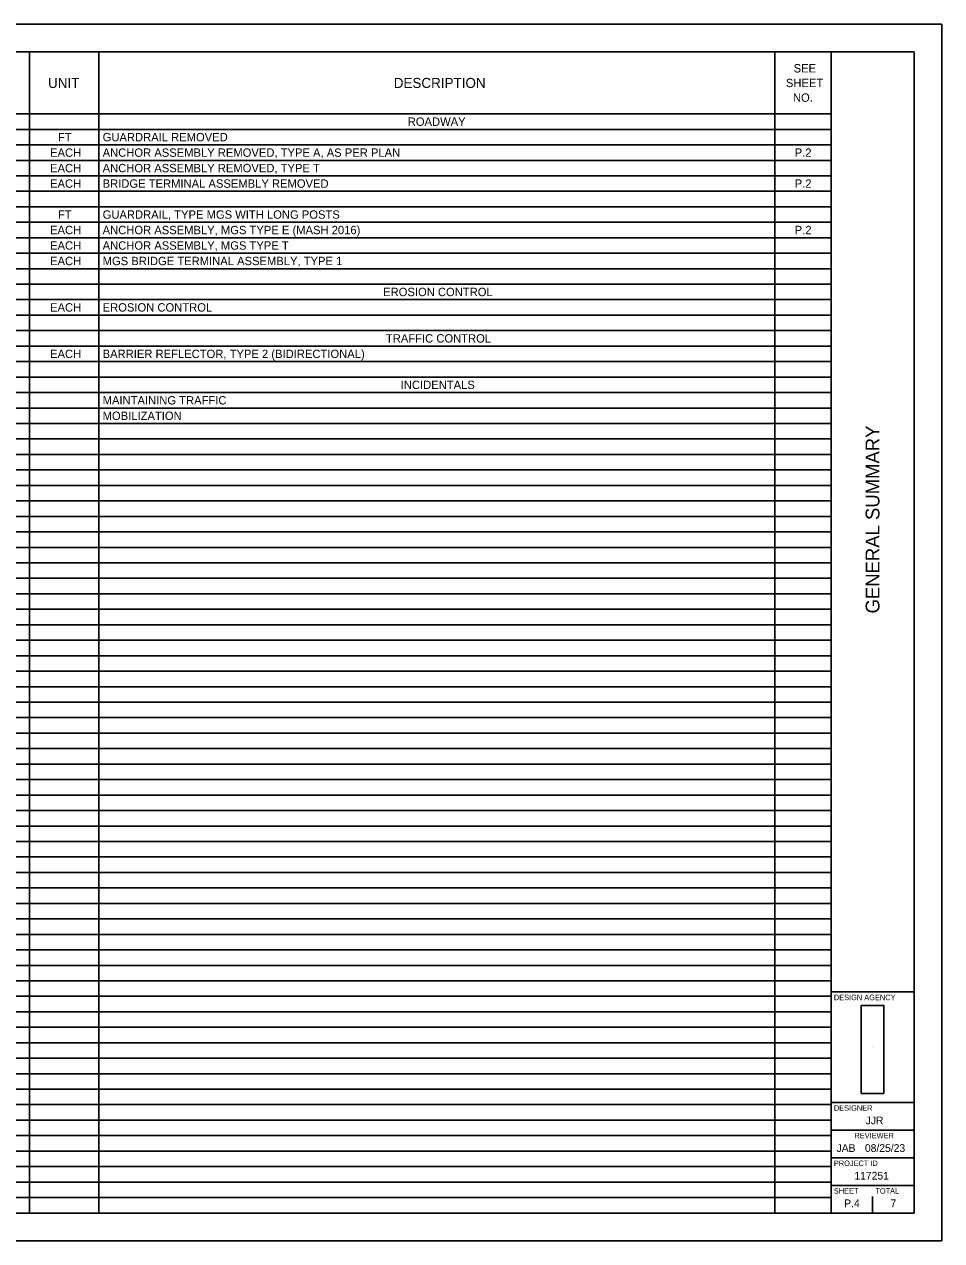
# Model space of a CAD drawing. Extents: x 0 to 34, y 0 to 22.
# Drawn here: x 17.41 to 34, y 0 to 22 of the extents above; entities that cross this region are included whole.
import ezdxf

# ---------------------------------------------------------------- set-up
doc = ezdxf.new("R2010")
doc.units = 0
for name, color, linetype in [('SH_Border', 7, 'Continuous'), ('SH_Cut_Line', 7, 'Continuous'), ('SH_Data', 7, 'Continuous'), ('SH_Text', 7, 'Continuous')]:
    doc.layers.add(name, color=color, linetype=linetype)

msp = doc.modelspace()

# ---------------------------------------------------------------- linework, layer by layer
at = {"layer": 'SH_Border'}
for p, q in [((32, 0.5), (32, 21.5)), ((32, 4.5), (33.5, 4.5)), ((32, 2.5), (33.5, 2.5)), ((32, 2), (33.5, 2)), ((32, 1.5), (33.5, 1.5)), ((32, 1), (33.5, 1))]:
    msp.add_line(p, q, dxfattribs=at)
msp.add_lwpolyline([(1.5, 21.5), (33.5, 21.5), (33.5, 0.5), (1.5, 0.5)], close=True, dxfattribs=at)
at = {"layer": 'SH_Cut_Line'}
msp.add_lwpolyline([(0, 0), (34, 0), (34, 22), (0, 22)], close=True, dxfattribs=at)
at = {"layer": 'SH_Data'}
for p, q in [((32.75, 3.5), (32.75, 3.5)), ((32.375, 0.675), (32.375, 0.675)), ((32.75, 0.5), (32.75, 0.8))]:
    msp.add_line(p, q, dxfattribs=at)
at = {"layer": 'SH_Text'}
for p, q in [((1.5, 21.5), (32, 21.5)), ((17.502, 21.5), (17.502, 0.5)), ((18.757, 21.5), (18.757, 0.5)), ((30.98, 21.5), (30.98, 0.5)), ((32, 21.5), (32, 0.5)), ((1.5, 20.38), (32, 20.38)), ((1.5, 20.1), (32, 20.1)), ((1.5, 19.82), (32, 19.82)), ((1.5, 19.54), (32, 19.54)), ((1.5, 19.26), (32, 19.26)), ((1.5, 18.98), (32, 18.98)), ((1.5, 18.7), (32, 18.7)), ((1.5, 18.42), (32, 18.42)), ((1.5, 18.14), (32, 18.14)), ((1.5, 17.86), (32, 17.86)), ((1.5, 17.58), (32, 17.58)), ((1.5, 17.3), (32, 17.3)), ((1.5, 17.02), (32, 17.02)), ((1.5, 16.74), (32, 16.74)), ((1.5, 16.46), (32, 16.46)), ((1.5, 16.18), (32, 16.18)), ((1.5, 15.9), (32, 15.9)), ((1.5, 15.62), (32, 15.62)), ((1.5, 15.34), (32, 15.34)), ((1.5, 15.06), (32, 15.06)), ((1.5, 14.78), (32, 14.78)), ((1.5, 14.5), (32, 14.5)), ((1.5, 14.22), (32, 14.22)), ((1.5, 13.94), (32, 13.94)), ((1.5, 13.66), (32, 13.66)), ((1.5, 13.38), (32, 13.38)), ((1.5, 13.1), (32, 13.1)), ((1.5, 12.82), (32, 12.82)), ((1.5, 12.54), (32, 12.54)), ((1.5, 12.26), (32, 12.26)), ((1.5, 11.98), (32, 11.98)), ((1.5, 11.7), (32, 11.7)), ((1.5, 11.42), (32, 11.42)), ((1.5, 11.14), (32, 11.14)), ((1.5, 10.86), (32, 10.86)), ((1.5, 10.58), (32, 10.58)), ((1.5, 10.3), (32, 10.3)), ((1.5, 10.02), (32, 10.02)), ((1.5, 9.74), (32, 9.74)), ((1.5, 9.46), (32, 9.46)), ((1.5, 9.18), (32, 9.18)), ((1.5, 8.9), (32, 8.9)), ((1.5, 8.62), (32, 8.62)), ((1.5, 8.34), (32, 8.34)), ((1.5, 8.06), (32, 8.06)), ((1.5, 7.78), (32, 7.78)), ((1.5, 7.5), (32, 7.5)), ((1.5, 7.22), (32, 7.22)), ((1.5, 6.94), (32, 6.94)), ((1.5, 6.66), (32, 6.66)), ((1.5, 6.38), (32, 6.38)), ((1.5, 6.1), (32, 6.1)), ((1.5, 5.82), (32, 5.82)), ((1.5, 5.54), (32, 5.54)), ((1.5, 5.26), (32, 5.26)), ((1.5, 4.98), (32, 4.98)), ((1.5, 4.7), (32, 4.7)), ((1.5, 4.42), (32, 4.42)), ((1.5, 4.14), (32, 4.14)), ((1.5, 3.86), (32, 3.86)), ((1.5, 3.58), (32, 3.58)), ((1.5, 3.3), (32, 3.3)), ((1.5, 3.02), (32, 3.02)), ((1.5, 2.74), (32, 2.74)), ((1.5, 2.46), (32, 2.46)), ((1.5, 2.18), (32, 2.18)), ((1.5, 1.9), (32, 1.9)), ((1.5, 1.62), (32, 1.62)), ((1.5, 1.34), (32, 1.34)), ((1.5, 1.06), (32, 1.06)), ((1.5, 0.78), (32, 0.78)), ((1.5, 0.5), (32, 0.5))]:
    msp.add_line(p, q, dxfattribs=at)
msp.add_lwpolyline([(32.956, 2.664), (32.956, 4.254), (32.544, 4.254), (32.544, 2.664)], close=True, dxfattribs=at)

# ---------------------------------------------------------------- texts
at = {"layer": 'SH_Data'}
msp.add_text('GENERAL SUMMARY', height=0.25, rotation=90, dxfattribs=at).set_placement((32.875, 11.344))
for s, height, p in [('DESIGN AGENCY', 0.1, (32.05, 4.35)), ('DESIGNER', 0.1, (32.05, 2.35)), ('JJR', 0.14, (32.624, 2.105)), ('REVIEWER', 0.1, (32.422, 1.85)), ('JAB', 0.14, (32.098, 1.605)), ('08/25/23', 0.14, (32.611, 1.605)), ('PROJECT ID', 0.1, (32.05, 1.35)), ('117251', 0.14, (32.421, 1.105)), ('SHEET', 0.1, (32.05, 0.85)), ('TOTAL', 0.1, (32.8, 0.85)), ('P.4', 0.14, (32.237, 0.605)), ('7', 0.14, (33.074, 0.605))]:
    msp.add_text(s, height=height, dxfattribs=at).set_placement(p)
at = {"layer": 'SH_Text'}
for s, height, p in [('SEE ', 0.1515, (31.322, 21.129)), ('UNIT', 0.1818, (17.836, 20.849)), ('DESCRIPTION', 0.18184, (24.089, 20.849)), ('SHEET ', 0.1515, (31.182, 20.864)), ('NO.', 0.1515, (31.31, 20.599)), ('ROADWAY', 0.1515, (24.342, 20.164)), ('FT', 0.1515, (18.016, 19.884)), ('GUARDRAIL REMOVED', 0.15153, (18.823, 19.884)), ('EACH', 0.1515, (17.872, 19.604)), ('ANCHOR ASSEMBLY REMOVED, TYPE A, AS PER PLAN', 0.15153, (18.823, 19.604)), ('P.2', 0.1515, (31.342, 19.604)), ('EACH', 0.1515, (17.872, 19.324)), ('ANCHOR ASSEMBLY REMOVED, TYPE T', 0.15153, (18.823, 19.324)), ('EACH', 0.1515, (17.872, 19.044)), ('BRIDGE TERMINAL ASSEMBLY REMOVED', 0.15153, (18.823, 19.044)), ('P.2', 0.1515, (31.342, 19.044)), ('FT', 0.1515, (18.016, 18.484)), ('GUARDRAIL, TYPE MGS WITH LONG POSTS', 0.15153, (18.823, 18.484)), ('EACH', 0.1515, (17.872, 18.204)), ('ANCHOR ASSEMBLY, MGS TYPE E (MASH 2016)', 0.15153, (18.823, 18.204)), ('P.2', 0.1515, (31.342, 18.204)), ('EACH', 0.1515, (17.872, 17.924)), ('ANCHOR ASSEMBLY, MGS TYPE T', 0.15153, (18.823, 17.924)), ('EACH', 0.1515, (17.872, 17.644)), ('MGS BRIDGE TERMINAL ASSEMBLY, TYPE 1', 0.15153, (18.823, 17.644)), ('EROSION CONTROL', 0.15153, (23.897, 17.084)), ('EACH', 0.1515, (17.872, 16.804)), ('EROSION CONTROL', 0.15153, (18.823, 16.804)), ('TRAFFIC CONTROL', 0.15153, (23.947, 16.244)), ('EACH', 0.1515, (17.872, 15.964)), ('BARRIER REFLECTOR, TYPE 2 (BIDIRECTIONAL)', 0.15153, (18.823, 15.964)), ('INCIDENTALS', 0.15153, (24.215, 15.404)), ('MAINTAINING TRAFFIC', 0.15153, (18.823, 15.124)), ('MOBILIZATION', 0.15153, (18.823, 14.844))]:
    msp.add_text(s, height=height, dxfattribs=at).set_placement(p)

doc.saveas('drawing.dxf')
